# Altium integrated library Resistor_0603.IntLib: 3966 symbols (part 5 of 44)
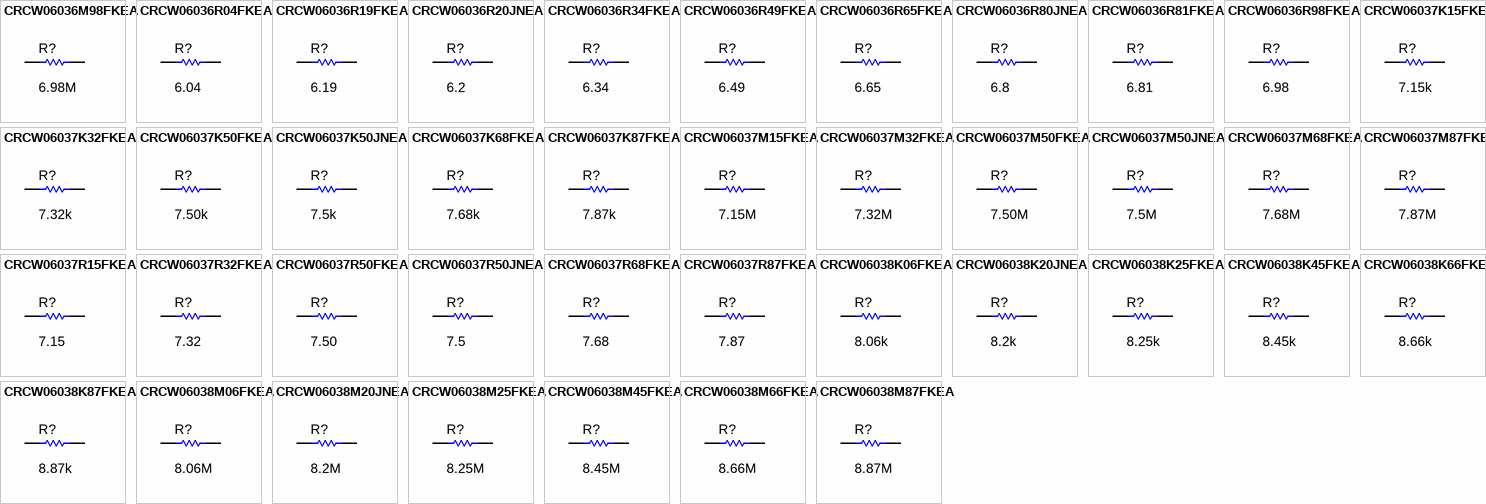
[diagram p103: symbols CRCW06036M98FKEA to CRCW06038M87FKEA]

## CRCW06038M66FKEA
designator R?  ValueDisplayed: 8.66M  (hidden comment: CRCW06038M66FKEA)
RES, 8.66 M, 1%, 0.1 W, 0603; Manufacturer: Vishay-Dale; CompType: Resistor; Value: 8.66Meg; Res_ohm: 8660000; Value_Code: 8M66; Tolerance_%: 1; Power_W: 0.1; Value2: 0.1W; VDC_V: 75; TempCo: 100 ppm/C; SizeArea_mm2: 1.28; SizeX_mm: 1.6; SizeY_mm: 0.8; EIA_Code: E96; U/M: EA; AEC Category: Q200; Green_Lifecycle: Active; Green_REACh: Passed
signal-integrity model Resistor
simulation model Resistor
footprint 0603
footprint 0603M
footprint 0603L
footprint 0603_HV
footprint 0603S
pins: 1, 2

## CRCW06038M87FKEA
designator R?  ValueDisplayed: 8.87M  (hidden comment: CRCW06038M87FKEA)
RES, 8.87 M, 1%, 0.1 W, 0603; Manufacturer: Vishay-Dale; CompType: Resistor; Value: 8.87Meg; Res_ohm: 8870000; Value_Code: 8M87; Tolerance_%: 1; Power_W: 0.1; Value2: 0.1W; VDC_V: 75; TempCo: 100 ppm/C; SizeArea_mm2: 1.28; SizeX_mm: 1.6; SizeY_mm: 0.8; EIA_Code: E96; U/M: EA; AEC Category: Q200
signal-integrity model Resistor
simulation model Resistor
footprint 0603
footprint 0603M
footprint 0603L
footprint 0603_HV
footprint 0603S
pins: 1, 2

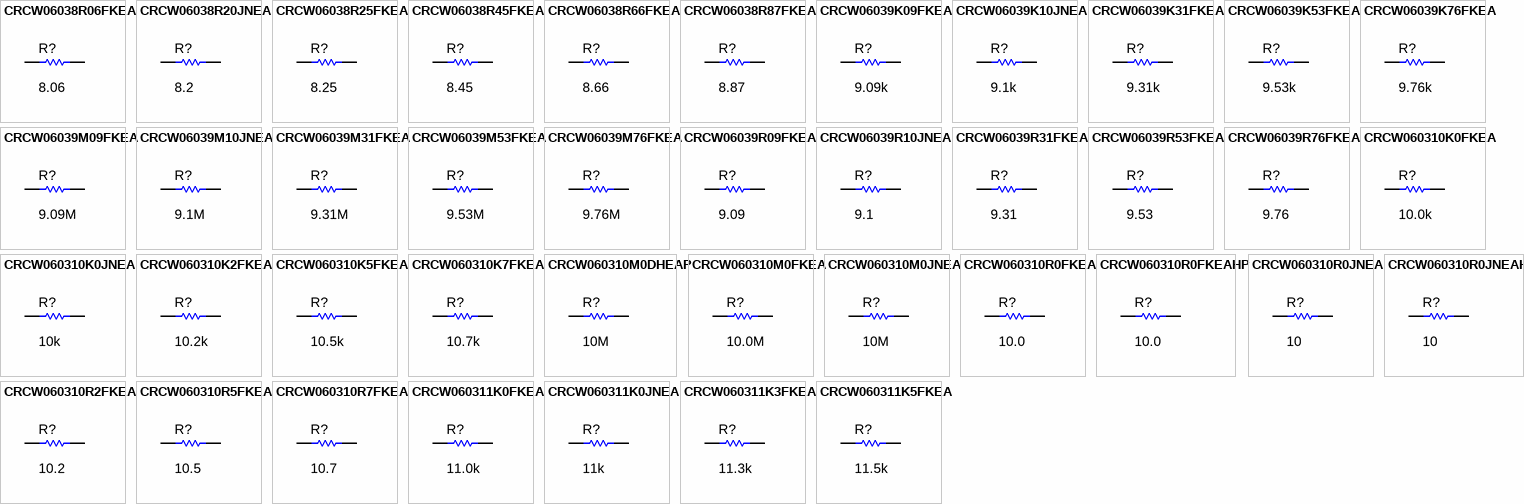
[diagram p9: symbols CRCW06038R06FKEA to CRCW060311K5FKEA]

## CRCW06038R06FKEA
designator R?  ValueDisplayed: 8.06  (hidden comment: CRCW06038R06FKEA)
RES, 8.06, 1%, 0.1 W, 0603; Manufacturer: Vishay-Dale; CompType: Resistor; Value: 8.06; Value_Code: 8R06; Tolerance_%: 1; Power_W: 0.1; Value2: 0.1W; VDC_V: 75; TempCo: 100 ppm/C; SizeArea_mm2: 1.28; SizeX_mm: 1.6; SizeY_mm: 0.8; EIA_Code: E96; U/M: EA; AEC Category: Q200
signal-integrity model Resistor
simulation model Resistor
footprint 0603
footprint 0603M
footprint 0603L
footprint 0603_HV
footprint 0603S
pins: 1, 2

## CRCW06038R20JNEA
designator R?  ValueDisplayed: 8.2  (hidden comment: CRCW06038R20JNEA)
RES, 8.2, 5%, 0.1 W, 0603; Manufacturer: Vishay-Dale; CompType: Resistor; Value: 8.2; Value_Code: 8R20; Tolerance_%: 5; Power_W: 0.1; Value2: 0.1W; VDC_V: 75; TempCo: 200 ppm/C; SizeArea_mm2: 1.28; SizeX_mm: 1.6; SizeY_mm: 0.8; SizeZ_mm: 1; EIA_Code: E24; U/M: EA; AEC Category: Q200
signal-integrity model Resistor
simulation model Resistor
footprint 0603
footprint 0603M
footprint 0603L
footprint 0603_HV
footprint 0603S
pins: 1, 2

## CRCW06038R25FKEA
designator R?  ValueDisplayed: 8.25  (hidden comment: CRCW06038R25FKEA)
RES, 8.25, 1%, 0.1 W, 0603; Manufacturer: Vishay-Dale; CompType: Resistor; Value: 8.25; Value_Code: 8R25; Tolerance_%: 1; Power_W: 0.1; Value2: 0.1W; VDC_V: 75; TempCo: 100 ppm/C; SizeArea_mm2: 1.28; SizeX_mm: 1.6; SizeY_mm: 0.8; EIA_Code: E96; U/M: EA; AEC Category: Q200
signal-integrity model Resistor
simulation model Resistor
footprint 0603
footprint 0603M
footprint 0603L
footprint 0603_HV
footprint 0603S
pins: 1, 2

## CRCW06038R45FKEA
designator R?  ValueDisplayed: 8.45  (hidden comment: CRCW06038R45FKEA)
RES, 8.45, 1%, 0.1 W, 0603; Manufacturer: Vishay-Dale; CompType: Resistor; Value: 8.45; Value_Code: 8R45; Tolerance_%: 1; Power_W: 0.1; Value2: 0.1W; VDC_V: 75; TempCo: 100 ppm/C; SizeArea_mm2: 1.28; SizeX_mm: 1.6; SizeY_mm: 0.8; EIA_Code: E96; U/M: EA; AEC Category: Q200
signal-integrity model Resistor
simulation model Resistor
footprint 0603
footprint 0603M
footprint 0603L
footprint 0603_HV
footprint 0603S
pins: 1, 2

## CRCW06038R66FKEA
designator R?  ValueDisplayed: 8.66  (hidden comment: CRCW06038R66FKEA)
RES, 8.66, 1%, 0.1 W, 0603; Manufacturer: Vishay-Dale; CompType: Resistor; Value: 8.66; Value_Code: 8R66; Tolerance_%: 1; Power_W: 0.1; Value2: 0.1W; VDC_V: 75; TempCo: 100 ppm/C; SizeArea_mm2: 1.28; SizeX_mm: 1.6; SizeY_mm: 0.8; EIA_Code: E96; U/M: EA; AEC Category: Q200
signal-integrity model Resistor
simulation model Resistor
footprint 0603
footprint 0603M
footprint 0603L
footprint 0603_HV
footprint 0603S
pins: 1, 2

## CRCW06038R87FKEA
designator R?  ValueDisplayed: 8.87  (hidden comment: CRCW06038R87FKEA)
RES, 8.87, 1%, 0.1 W, 0603; Manufacturer: Vishay-Dale; CompType: Resistor; Value: 8.87; Value_Code: 8R87; Tolerance_%: 1; Power_W: 0.1; Value2: 0.1W; VDC_V: 75; TempCo: 100 ppm/C; SizeArea_mm2: 1.28; SizeX_mm: 1.6; SizeY_mm: 0.8; EIA_Code: E96; U/M: EA; AEC Category: Q200
signal-integrity model Resistor
simulation model Resistor
footprint 0603
footprint 0603M
footprint 0603L
footprint 0603_HV
footprint 0603S
pins: 1, 2

## CRCW06039K09FKEA
designator R?  ValueDisplayed: 9.09k  (hidden comment: CRCW06039K09FKEA)
RES, 9.09 k, 1%, 0.1 W, 0603; Manufacturer: Vishay-Dale; CompType: Resistor; Value: 9.09k; Res_ohm: 9090; Value_Code: 9k09; Tolerance_%: 1; Power_W: 0.1; Value2: 0.1W; VDC_V: 75; TempCo: 100 ppm/C; SizeArea_mm2: 1.28; SizeX_mm: 1.6; SizeY_mm: 0.8; EIA_Code: E96; U/M: EA; AEC Category: Q200; Green_Lifecycle: Active; Green_REACh: Passed
signal-integrity model Resistor
simulation model Resistor
footprint 0603
footprint 0603M
footprint 0603L
footprint 0603_HV
footprint 0603S
pins: 1, 2

## CRCW06039K10JNEA
designator R?  ValueDisplayed: 9.1k  (hidden comment: CRCW06039K10JNEA)
RES, 9.1 k, 5%, 0.1 W, 0603; Manufacturer: Vishay-Dale; CompType: Resistor; Value: 9.1k; Res_ohm: 9100; Value_Code: 9k10; Tolerance_%: 5; Power_W: 0.1; Value2: 0.1W; VDC_V: 75; TempCo: 200 ppm/C; SizeArea_mm2: 1.28; SizeX_mm: 1.6; SizeY_mm: 0.8; SizeZ_mm: 1; EIA_Code: E24; U/M: EA; AEC Category: Q200; Green_Lifecycle: Active; Green_REACh: Passed
signal-integrity model Resistor
simulation model Resistor
footprint 0603
footprint 0603M
footprint 0603L
footprint 0603_HV
footprint 0603S
pins: 1, 2

## CRCW06039K31FKEA
designator R?  ValueDisplayed: 9.31k  (hidden comment: CRCW06039K31FKEA)
RES, 9.31 k, 1%, 0.1 W, 0603; Manufacturer: Vishay-Dale; CompType: Resistor; Value: 9.31k; Res_ohm: 9310; Value_Code: 9k31; Tolerance_%: 1; Power_W: 0.1; Value2: 0.1W; VDC_V: 75; TempCo: 100 ppm/C; SizeArea_mm2: 1.28; SizeX_mm: 1.6; SizeY_mm: 0.8; EIA_Code: E96; U/M: EA; AEC Category: Q200; Green_Lifecycle: Active; Green_REACh: Passed
signal-integrity model Resistor
simulation model Resistor
footprint 0603
footprint 0603M
footprint 0603L
footprint 0603_HV
footprint 0603S
pins: 1, 2

## CRCW06039K53FKEA
designator R?  ValueDisplayed: 9.53k  (hidden comment: CRCW06039K53FKEA)
RES, 9.53 k, 1%, 0.1 W, 0603; Manufacturer: Vishay-Dale; CompType: Resistor; Value: 9.53k; Res_ohm: 9530; Value_Code: 9k53; Tolerance_%: 1; Power_W: 0.1; Value2: 0.1W; VDC_V: 75; TempCo: 100 ppm/C; SizeArea_mm2: 1.28; SizeX_mm: 1.6; SizeY_mm: 0.8; EIA_Code: E96; U/M: EA; AEC Category: Q200; Green_Lifecycle: Active; Green_REACh: Passed
signal-integrity model Resistor
simulation model Resistor
footprint 0603
footprint 0603M
footprint 0603L
footprint 0603_HV
footprint 0603S
pins: 1, 2

## CRCW06039K76FKEA
designator R?  ValueDisplayed: 9.76k  (hidden comment: CRCW06039K76FKEA)
RES, 9.76 k, 1%, 0.1 W, 0603; Manufacturer: Vishay-Dale; CompType: Resistor; Value: 9.76k; Res_ohm: 9760; Value_Code: 9k76; Tolerance_%: 1; Power_W: 0.1; Value2: 0.1W; VDC_V: 75; TempCo: 100 ppm/C; SizeArea_mm2: 1.28; SizeX_mm: 1.6; SizeY_mm: 0.8; EIA_Code: E96; U/M: EA; AEC Category: Q200; Green_Lifecycle: Active; Green_REACh: Passed
signal-integrity model Resistor
simulation model Resistor
footprint 0603
footprint 0603M
footprint 0603L
footprint 0603_HV
footprint 0603S
pins: 1, 2

## CRCW06039M09FKEA
designator R?  ValueDisplayed: 9.09M  (hidden comment: CRCW06039M09FKEA)
RES, 9.09 M, 1%, 0.1 W, 0603; Manufacturer: Vishay-Dale; CompType: Resistor; Value: 9.09Meg; Res_ohm: 9090000; Value_Code: 9M09; Tolerance_%: 1; Power_W: 0.1; Value2: 0.1W; VDC_V: 75; TempCo: 100 ppm/C; SizeArea_mm2: 1.28; SizeX_mm: 1.6; SizeY_mm: 0.8; EIA_Code: E96; U/M: EA; AEC Category: Q200
signal-integrity model Resistor
simulation model Resistor
footprint 0603
footprint 0603M
footprint 0603L
footprint 0603_HV
footprint 0603S
pins: 1, 2

## CRCW06039M10JNEA
designator R?  ValueDisplayed: 9.1M  (hidden comment: CRCW06039M10JNEA)
RES, 9.1 M, 5%, 0.1 W, 0603; Manufacturer: Vishay-Dale; CompType: Resistor; Value: 9.1Meg; Res_ohm: 9100000; Value_Code: 9M10; Tolerance_%: 5; Power_W: 0.1; Value2: 0.1W; VDC_V: 75; TempCo: 200 ppm/C; SizeArea_mm2: 1.28; SizeX_mm: 1.6; SizeY_mm: 0.8; SizeZ_mm: 1; EIA_Code: E24; U/M: EA; AEC Category: Q200
signal-integrity model Resistor
simulation model Resistor
footprint 0603
footprint 0603M
footprint 0603L
footprint 0603_HV
footprint 0603S
pins: 1, 2

## CRCW06039M31FKEA
designator R?  ValueDisplayed: 9.31M  (hidden comment: CRCW06039M31FKEA)
RES, 9.31 M, 1%, 0.1 W, 0603; Manufacturer: Vishay-Dale; CompType: Resistor; Value: 9.31Meg; Res_ohm: 9310000; Value_Code: 9M31; Tolerance_%: 1; Power_W: 0.1; Value2: 0.1W; VDC_V: 75; TempCo: 100 ppm/C; SizeArea_mm2: 1.28; SizeX_mm: 1.6; SizeY_mm: 0.8; EIA_Code: E96; U/M: EA; AEC Category: Q200
signal-integrity model Resistor
simulation model Resistor
footprint 0603
footprint 0603M
footprint 0603L
footprint 0603_HV
footprint 0603S
pins: 1, 2

## CRCW06039M53FKEA
designator R?  ValueDisplayed: 9.53M  (hidden comment: CRCW06039M53FKEA)
RES, 9.53 M, 1%, 0.1 W, 0603; Manufacturer: Vishay-Dale; CompType: Resistor; Value: 9.53Meg; Res_ohm: 9530000; Value_Code: 9M53; Tolerance_%: 1; Power_W: 0.1; Value2: 0.1W; VDC_V: 75; TempCo: 100 ppm/C; SizeArea_mm2: 1.28; SizeX_mm: 1.6; SizeY_mm: 0.8; EIA_Code: E96; U/M: EA; AEC Category: Q200
signal-integrity model Resistor
simulation model Resistor
footprint 0603
footprint 0603M
footprint 0603L
footprint 0603_HV
footprint 0603S
pins: 1, 2

## CRCW06039M76FKEA
designator R?  ValueDisplayed: 9.76M  (hidden comment: CRCW06039M76FKEA)
RES, 9.76 M, 1%, 0.1 W, 0603; Manufacturer: Vishay-Dale; CompType: Resistor; Value: 9.76Meg; Res_ohm: 9760000; Value_Code: 9M76; Tolerance_%: 1; Power_W: 0.1; Value2: 0.1W; VDC_V: 75; TempCo: 100 ppm/C; SizeArea_mm2: 1.28; SizeX_mm: 1.6; SizeY_mm: 0.8; EIA_Code: E96; U/M: EA; AEC Category: Q200
signal-integrity model Resistor
simulation model Resistor
footprint 0603
footprint 0603M
footprint 0603L
footprint 0603_HV
footprint 0603S
pins: 1, 2

## CRCW06039R09FKEA
designator R?  ValueDisplayed: 9.09  (hidden comment: CRCW06039R09FKEA)
RES, 9.09, 1%, 0.1 W, 0603; Manufacturer: Vishay-Dale; CompType: Resistor; Value: 9.09; Value_Code: 9R09; Tolerance_%: 1; Power_W: 0.1; Value2: 0.1W; VDC_V: 75; TempCo: 100 ppm/C; SizeArea_mm2: 1.28; SizeX_mm: 1.6; SizeY_mm: 0.8; EIA_Code: E96; U/M: EA; AEC Category: Q200; Green_Lifecycle: Active; Green_REACh: Passed
signal-integrity model Resistor
simulation model Resistor
footprint 0603
footprint 0603M
footprint 0603L
footprint 0603_HV
footprint 0603S
pins: 1, 2

## CRCW06039R10JNEA
designator R?  ValueDisplayed: 9.1  (hidden comment: CRCW06039R10JNEA)
RES, 9.1, 5%, 0.1 W, 0603; Manufacturer: Vishay-Dale; CompType: Resistor; Value: 9.1; Value_Code: 9R10; Tolerance_%: 5; Power_W: 0.1; Value2: 0.1W; VDC_V: 75; TempCo: 200 ppm/C; SizeArea_mm2: 1.28; SizeX_mm: 1.6; SizeY_mm: 0.8; SizeZ_mm: 1; EIA_Code: E24; U/M: EA; AEC Category: Q200
signal-integrity model Resistor
simulation model Resistor
footprint 0603
footprint 0603M
footprint 0603L
footprint 0603_HV
footprint 0603S
pins: 1, 2

## CRCW06039R31FKEA
designator R?  ValueDisplayed: 9.31  (hidden comment: CRCW06039R31FKEA)
RES, 9.31, 1%, 0.1 W, 0603; Manufacturer: Vishay-Dale; CompType: Resistor; Value: 9.31; Value_Code: 9R31; Tolerance_%: 1; Power_W: 0.1; Value2: 0.1W; VDC_V: 75; TempCo: 100 ppm/C; SizeArea_mm2: 1.28; SizeX_mm: 1.6; SizeY_mm: 0.8; EIA_Code: E96; U/M: EA; AEC Category: Q200
signal-integrity model Resistor
simulation model Resistor
footprint 0603
footprint 0603M
footprint 0603L
footprint 0603_HV
footprint 0603S
pins: 1, 2

## CRCW06039R53FKEA
designator R?  ValueDisplayed: 9.53  (hidden comment: CRCW06039R53FKEA)
RES, 9.53, 1%, 0.1 W, 0603; Manufacturer: Vishay-Dale; CompType: Resistor; Value: 9.53; Value_Code: 9R53; Tolerance_%: 1; Power_W: 0.1; Value2: 0.1W; VDC_V: 75; TempCo: 100 ppm/C; SizeArea_mm2: 1.28; SizeX_mm: 1.6; SizeY_mm: 0.8; EIA_Code: E96; U/M: EA; AEC Category: Q200
signal-integrity model Resistor
simulation model Resistor
footprint 0603
footprint 0603M
footprint 0603L
footprint 0603_HV
footprint 0603S
pins: 1, 2

## CRCW06039R76FKEA
designator R?  ValueDisplayed: 9.76  (hidden comment: CRCW06039R76FKEA)
RES, 9.76, 1%, 0.1 W, 0603; Manufacturer: Vishay-Dale; CompType: Resistor; Value: 9.76; Value_Code: 9R76; Tolerance_%: 1; Power_W: 0.1; Value2: 0.1W; VDC_V: 75; TempCo: 100 ppm/C; SizeArea_mm2: 1.28; SizeX_mm: 1.6; SizeY_mm: 0.8; EIA_Code: E96; U/M: EA; AEC Category: Q200
signal-integrity model Resistor
simulation model Resistor
footprint 0603
footprint 0603M
footprint 0603L
footprint 0603_HV
footprint 0603S
pins: 1, 2

## CRCW060310K0FKEA
designator R?  ValueDisplayed: 10.0k  (hidden comment: CRCW060310K0FKEA)
RES, 10.0 k, 1%, 0.1 W, 0603; Manufacturer: Vishay-Dale; CompType: Resistor; Value: 10.0k; Res_ohm: 10000; Value_Code: 10k0; Tolerance_%: 1; Power_W: 0.1; Value2: 0.1W; VDC_V: 75; TempCo: 100 ppm/C; SizeArea_mm2: 1.28; SizeX_mm: 1.6; SizeY_mm: 0.8; EIA_Code: E96; U/M: EA; AEC Category: Q200; Green_Lifecycle: Active; Green_REACh: Passed
signal-integrity model Resistor
simulation model Resistor
footprint 0603
footprint 0603M
footprint 0603L
footprint 0603_HV
footprint 0603S
pins: 1, 2

## CRCW060310K0JNEA
designator R?  ValueDisplayed: 10k  (hidden comment: CRCW060310K0JNEA)
RES, 10 k, 5%, 0.1 W, 0603; Manufacturer: Vishay-Dale; CompType: Resistor; Value: 10k; Res_ohm: 10000; Value_Code: 10k0; Tolerance_%: 5; Power_W: 0.1; Value2: 0.1W; VDC_V: 75; TempCo: 200 ppm/C; SizeArea_mm2: 1.28; SizeX_mm: 1.6; SizeY_mm: 0.8; SizeZ_mm: 1; EIA_Code: E24; U/M: EA; AEC Category: Q200; Green_Lifecycle: Active; Green_REACh: Passed
signal-integrity model Resistor
simulation model Resistor
footprint 0603
footprint 0603M
footprint 0603L
footprint 0603_HV
footprint 0603S
pins: 1, 2

## CRCW060310K2FKEA
designator R?  ValueDisplayed: 10.2k  (hidden comment: CRCW060310K2FKEA)
RES, 10.2 k, 1%, 0.1 W, 0603; Manufacturer: Vishay-Dale; CompType: Resistor; Value: 10.2k; Res_ohm: 10200; Value_Code: 10k2; Tolerance_%: 1; Power_W: 0.1; Value2: 0.1W; VDC_V: 75; TempCo: 100 ppm/C; SizeArea_mm2: 1.28; SizeX_mm: 1.6; SizeY_mm: 0.8; EIA_Code: E96; U/M: EA; AEC Category: Q200; Green_Lifecycle: Active; Green_REACh: Passed
signal-integrity model Resistor
simulation model Resistor
footprint 0603
footprint 0603M
footprint 0603L
footprint 0603_HV
footprint 0603S
pins: 1, 2

## CRCW060310K5FKEA
designator R?  ValueDisplayed: 10.5k  (hidden comment: CRCW060310K5FKEA)
RES, 10.5 k, 1%, 0.1 W, 0603; Manufacturer: Vishay-Dale; CompType: Resistor; Value: 10.5k; Res_ohm: 10500; Value_Code: 10k5; Tolerance_%: 1; Power_W: 0.1; Value2: 0.1W; VDC_V: 75; TempCo: 100 ppm/C; SizeArea_mm2: 1.28; SizeX_mm: 1.6; SizeY_mm: 0.8; EIA_Code: E96; U/M: EA; AEC Category: Q200; Green_Lifecycle: Active; Green_REACh: Passed
signal-integrity model Resistor
simulation model Resistor
footprint 0603
footprint 0603M
footprint 0603L
footprint 0603_HV
footprint 0603S
pins: 1, 2

## CRCW060310K7FKEA
designator R?  ValueDisplayed: 10.7k  (hidden comment: CRCW060310K7FKEA)
RES, 10.7 k, 1%, 0.1 W, 0603; Manufacturer: Vishay-Dale; CompType: Resistor; Value: 10.7k; Res_ohm: 10700; Value_Code: 10k7; Tolerance_%: 1; Power_W: 0.1; Value2: 0.1W; VDC_V: 75; TempCo: 100 ppm/C; SizeArea_mm2: 1.28; SizeX_mm: 1.6; SizeY_mm: 0.8; EIA_Code: E96; U/M: EA; AEC Category: Q200; Green_Lifecycle: Active; Green_REACh: Passed
signal-integrity model Resistor
simulation model Resistor
footprint 0603
footprint 0603M
footprint 0603L
footprint 0603_HV
footprint 0603S
pins: 1, 2

## CRCW060310M0DHEAP
designator R?  ValueDisplayed: 10M  (hidden comment: CRCW060310M0DHEAP)
RES, 10 M, 0.5%, 0.1 W, AEC-Q200 Grade 0, 0603; Manufacturer: Vishay-Dale; CompType: Resistor; Value: 10Meg; Res_ohm: 10000000; Value_Code: 10M0; Tolerance_%: 0.5; Power_W: 0.1; Value2: 0.1W; VDC_V: 75; TempCo: 50 ppm/C; SizeArea_mm2: 1.28; SizeX_mm: 1.6; SizeY_mm: 0.8; SizeZ_mm: 1; EIA_Code: E24; U/M: EA; AEC Category: Q200; AEC Qualified: Y; AEC Grade: 0
signal-integrity model Resistor
simulation model Resistor
footprint 0603
footprint 0603M
footprint 0603L
footprint 0603_HV
footprint 0603S
pins: 1, 2

## CRCW060310M0FKEA
designator R?  ValueDisplayed: 10.0M  (hidden comment: CRCW060310M0FKEA)
RES, 10.0 M, 1%, 0.1 W, 0603; Manufacturer: Vishay-Dale; CompType: Resistor; Value: 10.0Meg; Res_ohm: 10000000; Value_Code: 10M0; Tolerance_%: 1; Power_W: 0.1; Value2: 0.1W; VDC_V: 75; TempCo: 100 ppm/C; SizeArea_mm2: 1.28; SizeX_mm: 1.6; SizeY_mm: 0.8; EIA_Code: E96; U/M: EA; AEC Category: Q200; Green_Lifecycle: Active; Green_REACh: Passed
signal-integrity model Resistor
simulation model Resistor
footprint 0603
footprint 0603M
footprint 0603L
footprint 0603_HV
footprint 0603S
pins: 1, 2

## CRCW060310M0JNEA
designator R?  ValueDisplayed: 10M  (hidden comment: CRCW060310M0JNEA)
RES, 10 M, 5%, 0.1 W, 0603; Manufacturer: Vishay-Dale; CompType: Resistor; Value: 10Meg; Res_ohm: 10000000; Value_Code: 10M0; Tolerance_%: 5; Power_W: 0.1; Value2: 0.1W; VDC_V: 75; TempCo: 200 ppm/C; SizeArea_mm2: 1.28; SizeX_mm: 1.6; SizeY_mm: 0.8; SizeZ_mm: 1; EIA_Code: E24; U/M: EA; AEC Category: Q200; Green_Lifecycle: Active; Green_REACh: Passed
signal-integrity model Resistor
simulation model Resistor
footprint 0603
footprint 0603M
footprint 0603L
footprint 0603_HV
footprint 0603S
pins: 1, 2

## CRCW060310R0FKEA
designator R?  ValueDisplayed: 10.0  (hidden comment: CRCW060310R0FKEA)
RES, 10.0, 1%, 0.1 W, 0603; Manufacturer: Vishay-Dale; CompType: Resistor; Value: 10.0; Res_ohm: 10; Value_Code: 10R0; Tolerance_%: 1; Power_W: 0.1; Value2: 0.1W; VDC_V: 75; TempCo: 100 ppm/C; SizeArea_mm2: 1.28; SizeX_mm: 1.6; SizeY_mm: 0.8; EIA_Code: E96; U/M: EA; AEC Category: Q200; Green_Lifecycle: Active; Green_REACh: Passed
signal-integrity model Resistor
simulation model Resistor
footprint 0603
footprint 0603M
footprint 0603L
footprint 0603_HV
footprint 0603S
pins: 1, 2

## CRCW060310R0FKEAHP
designator R?  ValueDisplayed: 10.0  (hidden comment: CRCW060310R0FKEAHP)
RES, 10.0, 1%, 0.25 W, 0603; Manufacturer: Vishay-Dale; CompType: Resistor; Value: 10.0; Res_ohm: 10; Value_Code: 10R0; Tolerance_%: 1; Power_W: 0.25; Value2: 0.25W; VDC_V: 75; TempCo: 100 ppm/C; SizeArea_mm2: 1.28; SizeX_mm: 1.6; SizeY_mm: 0.8; EIA_Code: E96; U/M: EA; AEC Category: Q200; Green_Lifecycle: Active; Green_REACh: Passed
signal-integrity model Resistor
simulation model Resistor
footprint 0603
footprint 0603M
footprint 0603L
footprint 0603_HV
footprint 0603S
pins: 1, 2

## CRCW060310R0JNEA
designator R?  ValueDisplayed: 10  (hidden comment: CRCW060310R0JNEA)
RES, 10, 5%, 0.1 W, 0603; Manufacturer: Vishay-Dale; CompType: Resistor; Value: 10; Value_Code: 10R0; Tolerance_%: 5; Power_W: 0.1; Value2: 0.1W; VDC_V: 75; TempCo: 200 ppm/C; SizeArea_mm2: 1.28; SizeX_mm: 1.6; SizeY_mm: 0.8; SizeZ_mm: 1; EIA_Code: E24; U/M: EA; AEC Category: Q200; Green_Lifecycle: Active; Green_REACh: Passed
signal-integrity model Resistor
simulation model Resistor
footprint 0603
footprint 0603M
footprint 0603L
footprint 0603_HV
footprint 0603S
pins: 1, 2

## CRCW060310R0JNEAHP
designator R?  ValueDisplayed: 10  (hidden comment: CRCW060310R0JNEAHP)
RES, 10, 5%, 0.25 W, 0603; Manufacturer: Vishay-Dale; CompType: Resistor; Value: 10; Value_Code: 10R0; Tolerance_%: 5; Power_W: 0.25; Value2: 0.25W; VDC_V: 75; TempCo: 200 ppm/C; SizeArea_mm2: 1.28; SizeX_mm: 1.6; SizeY_mm: 0.8; SizeZ_mm: 1; EIA_Code: E24; U/M: EA; AEC Category: Q200; Green_Lifecycle: Active; Green_REACh: Passed
signal-integrity model Resistor
simulation model Resistor
footprint 0603
footprint 0603M
footprint 0603L
footprint 0603_HV
footprint 0603S
pins: 1, 2

## CRCW060310R2FKEA
designator R?  ValueDisplayed: 10.2  (hidden comment: CRCW060310R2FKEA)
RES, 10.2, 1%, 0.1 W, 0603; Manufacturer: Vishay-Dale; CompType: Resistor; Value: 10.2; Value_Code: 10R2; Tolerance_%: 1; Power_W: 0.1; Value2: 0.1W; VDC_V: 75; TempCo: 100 ppm/C; SizeArea_mm2: 1.28; SizeX_mm: 1.6; SizeY_mm: 0.8; EIA_Code: E96; U/M: EA; AEC Category: Q200
signal-integrity model Resistor
simulation model Resistor
footprint 0603
footprint 0603M
footprint 0603L
footprint 0603_HV
footprint 0603S
pins: 1, 2

## CRCW060310R5FKEA
designator R?  ValueDisplayed: 10.5  (hidden comment: CRCW060310R5FKEA)
RES, 10.5, 1%, 0.1 W, 0603; Manufacturer: Vishay-Dale; CompType: Resistor; Value: 10.5; Value_Code: 10R5; Tolerance_%: 1; Power_W: 0.1; Value2: 0.1W; VDC_V: 75; TempCo: 100 ppm/C; SizeArea_mm2: 1.28; SizeX_mm: 1.6; SizeY_mm: 0.8; EIA_Code: E96; U/M: EA; AEC Category: Q200
signal-integrity model Resistor
simulation model Resistor
footprint 0603
footprint 0603M
footprint 0603L
footprint 0603_HV
footprint 0603S
pins: 1, 2

## CRCW060310R7FKEA
designator R?  ValueDisplayed: 10.7  (hidden comment: CRCW060310R7FKEA)
RES, 10.7, 1%, 0.1 W, 0603; Manufacturer: Vishay-Dale; CompType: Resistor; Value: 10.7; Value_Code: 10R7; Tolerance_%: 1; Power_W: 0.1; Value2: 0.1W; VDC_V: 75; TempCo: 100 ppm/C; SizeArea_mm2: 1.28; SizeX_mm: 1.6; SizeY_mm: 0.8; EIA_Code: E96; U/M: EA; AEC Category: Q200
signal-integrity model Resistor
simulation model Resistor
footprint 0603
footprint 0603M
footprint 0603L
footprint 0603_HV
footprint 0603S
pins: 1, 2

## CRCW060311K0FKEA
designator R?  ValueDisplayed: 11.0k  (hidden comment: CRCW060311K0FKEA)
RES, 11.0 k, 1%, 0.1 W, 0603; Manufacturer: Vishay-Dale; CompType: Resistor; Value: 11.0k; Res_ohm: 11000; Value_Code: 11k0; Tolerance_%: 1; Power_W: 0.1; Value2: 0.1W; VDC_V: 75; TempCo: 100 ppm/C; SizeArea_mm2: 1.28; SizeX_mm: 1.6; SizeY_mm: 0.8; EIA_Code: E96; U/M: EA; AEC Category: Q200; Green_Lifecycle: Not Set; Green_REACh: Incomplete
signal-integrity model Resistor
simulation model Resistor
footprint 0603
footprint 0603M
footprint 0603L
footprint 0603_HV
footprint 0603S
pins: 1, 2

## CRCW060311K0JNEA
designator R?  ValueDisplayed: 11k  (hidden comment: CRCW060311K0JNEA)
RES, 11 k, 5%, 0.1 W, 0603; Manufacturer: Vishay-Dale; CompType: Resistor; Value: 11k; Res_ohm: 11000; Value_Code: 11k0; Tolerance_%: 5; Power_W: 0.1; Value2: 0.1W; VDC_V: 75; TempCo: 200 ppm/C; SizeArea_mm2: 1.28; SizeX_mm: 1.6; SizeY_mm: 0.8; SizeZ_mm: 1; EIA_Code: E24; U/M: EA; AEC Category: Q200
signal-integrity model Resistor
simulation model Resistor
footprint 0603
footprint 0603M
footprint 0603L
footprint 0603_HV
footprint 0603S
pins: 1, 2

## CRCW060311K3FKEA
designator R?  ValueDisplayed: 11.3k  (hidden comment: CRCW060311K3FKEA)
RES, 11.3 k, 1%, 0.1 W, 0603; Manufacturer: Vishay-Dale; CompType: Resistor; Value: 11.3k; Res_ohm: 11300; Value_Code: 11k3; Tolerance_%: 1; Power_W: 0.1; Value2: 0.1W; VDC_V: 75; TempCo: 100 ppm/C; SizeArea_mm2: 1.28; SizeX_mm: 1.6; SizeY_mm: 0.8; EIA_Code: E96; U/M: EA; AEC Category: Q200; Green_Lifecycle: Active; Green_REACh: Passed
signal-integrity model Resistor
simulation model Resistor
footprint 0603
footprint 0603M
footprint 0603L
footprint 0603_HV
footprint 0603S
pins: 1, 2

## CRCW060311K5FKEA
designator R?  ValueDisplayed: 11.5k  (hidden comment: CRCW060311K5FKEA)
RES, 11.5 k, 1%, 0.1 W, 0603; Manufacturer: Vishay-Dale; CompType: Resistor; Value: 11.5k; Res_ohm: 11500; Value_Code: 11k5; Tolerance_%: 1; Power_W: 0.1; Value2: 0.1W; VDC_V: 75; TempCo: 100 ppm/C; SizeArea_mm2: 1.28; SizeX_mm: 1.6; SizeY_mm: 0.8; EIA_Code: E96; U/M: EA; AEC Category: Q200; Green_Lifecycle: Active; Green_REACh: Passed
signal-integrity model Resistor
simulation model Resistor
footprint 0603
footprint 0603M
footprint 0603L
footprint 0603_HV
footprint 0603S
pins: 1, 2

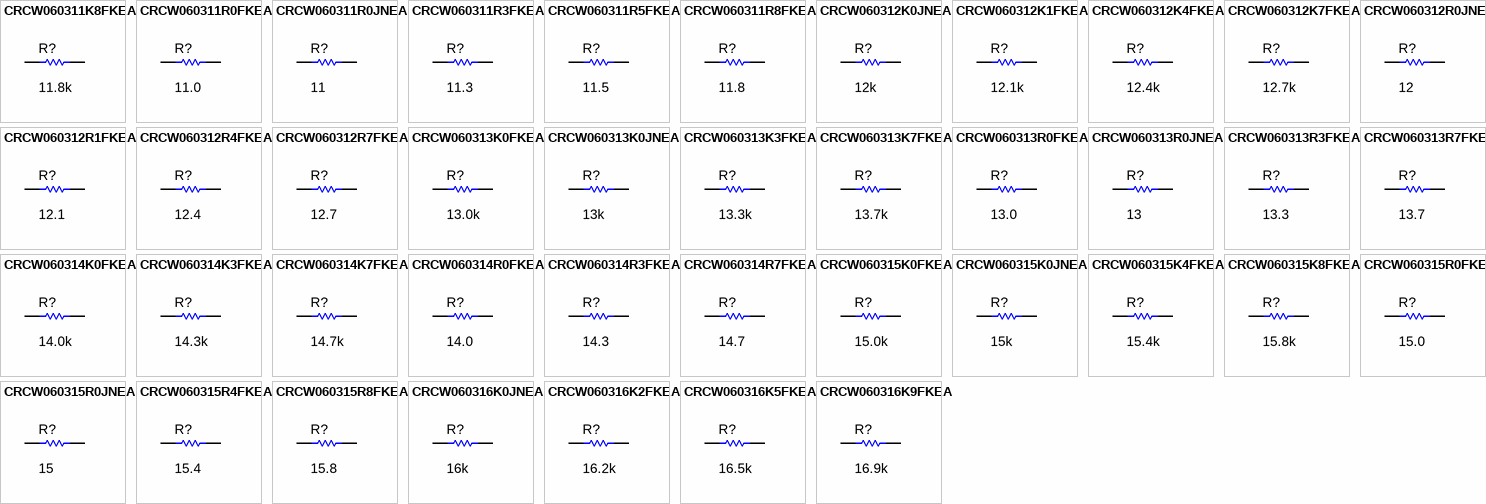
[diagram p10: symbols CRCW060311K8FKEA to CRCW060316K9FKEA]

## CRCW060311K8FKEA
designator R?  ValueDisplayed: 11.8k  (hidden comment: CRCW060311K8FKEA)
RES, 11.8 k, 1%, 0.1 W, 0603; Manufacturer: Vishay-Dale; CompType: Resistor; Value: 11.8k; Res_ohm: 11800; Value_Code: 11k8; Tolerance_%: 1; Power_W: 0.1; Value2: 0.1W; VDC_V: 75; TempCo: 100 ppm/C; SizeArea_mm2: 1.28; SizeX_mm: 1.6; SizeY_mm: 0.8; EIA_Code: E96; U/M: EA; AEC Category: Q200; Green_Lifecycle: Active; Green_REACh: Passed
signal-integrity model Resistor
simulation model Resistor
footprint 0603
footprint 0603M
footprint 0603L
footprint 0603_HV
footprint 0603S
pins: 1, 2

## CRCW060311R0FKEA
designator R?  ValueDisplayed: 11.0  (hidden comment: CRCW060311R0FKEA)
RES, 11.0, 1%, 0.1 W, 0603; Manufacturer: Vishay-Dale; CompType: Resistor; Value: 11.0; Res_ohm: 11; Value_Code: 11R0; Tolerance_%: 1; Power_W: 0.1; Value2: 0.1W; VDC_V: 75; TempCo: 100 ppm/C; SizeArea_mm2: 1.28; SizeX_mm: 1.6; SizeY_mm: 0.8; EIA_Code: E96; U/M: EA; AEC Category: Q200
signal-integrity model Resistor
simulation model Resistor
footprint 0603
footprint 0603M
footprint 0603L
footprint 0603_HV
footprint 0603S
pins: 1, 2

## CRCW060311R0JNEA
designator R?  ValueDisplayed: 11  (hidden comment: CRCW060311R0JNEA)
RES, 11, 5%, 0.1 W, 0603; Manufacturer: Vishay-Dale; CompType: Resistor; Value: 11; Value_Code: 11R0; Tolerance_%: 5; Power_W: 0.1; Value2: 0.1W; VDC_V: 75; TempCo: 200 ppm/C; SizeArea_mm2: 1.28; SizeX_mm: 1.6; SizeY_mm: 0.8; SizeZ_mm: 1; EIA_Code: E24; U/M: EA; AEC Category: Q200
signal-integrity model Resistor
simulation model Resistor
footprint 0603
footprint 0603M
footprint 0603L
footprint 0603_HV
footprint 0603S
pins: 1, 2

## CRCW060311R3FKEA
designator R?  ValueDisplayed: 11.3  (hidden comment: CRCW060311R3FKEA)
RES, 11.3, 1%, 0.1 W, 0603; Manufacturer: Vishay-Dale; CompType: Resistor; Value: 11.3; Value_Code: 11R3; Tolerance_%: 1; Power_W: 0.1; Value2: 0.1W; VDC_V: 75; TempCo: 100 ppm/C; SizeArea_mm2: 1.28; SizeX_mm: 1.6; SizeY_mm: 0.8; EIA_Code: E96; U/M: EA; AEC Category: Q200
signal-integrity model Resistor
simulation model Resistor
footprint 0603
footprint 0603M
footprint 0603L
footprint 0603_HV
footprint 0603S
pins: 1, 2

## CRCW060311R5FKEA
designator R?  ValueDisplayed: 11.5  (hidden comment: CRCW060311R5FKEA)
RES, 11.5, 1%, 0.1 W, 0603; Manufacturer: Vishay-Dale; CompType: Resistor; Value: 11.5; Value_Code: 11R5; Tolerance_%: 1; Power_W: 0.1; Value2: 0.1W; VDC_V: 75; TempCo: 100 ppm/C; SizeArea_mm2: 1.28; SizeX_mm: 1.6; SizeY_mm: 0.8; EIA_Code: E96; U/M: EA; AEC Category: Q200
signal-integrity model Resistor
simulation model Resistor
footprint 0603
footprint 0603M
footprint 0603L
footprint 0603_HV
footprint 0603S
pins: 1, 2

## CRCW060311R8FKEA
designator R?  ValueDisplayed: 11.8  (hidden comment: CRCW060311R8FKEA)
RES, 11.8, 1%, 0.1 W, 0603; Manufacturer: Vishay-Dale; CompType: Resistor; Value: 11.8; Value_Code: 11R8; Tolerance_%: 1; Power_W: 0.1; Value2: 0.1W; VDC_V: 75; TempCo: 100 ppm/C; SizeArea_mm2: 1.28; SizeX_mm: 1.6; SizeY_mm: 0.8; EIA_Code: E96; U/M: EA; AEC Category: Q200
signal-integrity model Resistor
simulation model Resistor
footprint 0603
footprint 0603M
footprint 0603L
footprint 0603_HV
footprint 0603S
pins: 1, 2

## CRCW060312K0JNEA
designator R?  ValueDisplayed: 12k  (hidden comment: CRCW060312K0JNEA)
RES, 12 k, 5%, 0.1 W, 0603; Manufacturer: Vishay-Dale; CompType: Resistor; Value: 12k; Res_ohm: 12000; Value_Code: 12k0; Tolerance_%: 5; Power_W: 0.1; Value2: 0.1W; VDC_V: 75; TempCo: 200 ppm/C; SizeArea_mm2: 1.28; SizeX_mm: 1.6; SizeY_mm: 0.8; SizeZ_mm: 1; EIA_Code: E24; U/M: EA; AEC Category: Q200; Green_Lifecycle: Active; Green_REACh: Passed
signal-integrity model Resistor
simulation model Resistor
footprint 0603
footprint 0603M
footprint 0603L
footprint 0603_HV
footprint 0603S
pins: 1, 2

## CRCW060312K1FKEA
designator R?  ValueDisplayed: 12.1k  (hidden comment: CRCW060312K1FKEA)
RES, 12.1 k, 1%, 0.1 W, 0603; Manufacturer: Vishay-Dale; CompType: Resistor; Value: 12.1k; Res_ohm: 12100; Value_Code: 12k1; Tolerance_%: 1; Power_W: 0.1; Value2: 0.1W; VDC_V: 75; TempCo: 100 ppm/C; SizeArea_mm2: 1.28; SizeX_mm: 1.6; SizeY_mm: 0.8; EIA_Code: E96; U/M: EA; AEC Category: Q200; Green_Lifecycle: Active; Green_REACh: Passed
signal-integrity model Resistor
simulation model Resistor
footprint 0603
footprint 0603M
footprint 0603L
footprint 0603_HV
footprint 0603S
pins: 1, 2

## CRCW060312K4FKEA
designator R?  ValueDisplayed: 12.4k  (hidden comment: CRCW060312K4FKEA)
RES, 12.4 k, 1%, 0.1 W, 0603; Manufacturer: Vishay-Dale; CompType: Resistor; Value: 12.4k; Res_ohm: 12400; Value_Code: 12k4; Tolerance_%: 1; Power_W: 0.1; Value2: 0.1W; VDC_V: 75; TempCo: 100 ppm/C; SizeArea_mm2: 1.28; SizeX_mm: 1.6; SizeY_mm: 0.8; EIA_Code: E96; U/M: EA; AEC Category: Q200; Green_Lifecycle: Active; Green_REACh: Passed
signal-integrity model Resistor
simulation model Resistor
footprint 0603
footprint 0603M
footprint 0603L
footprint 0603_HV
footprint 0603S
pins: 1, 2

## CRCW060312K7FKEA
designator R?  ValueDisplayed: 12.7k  (hidden comment: CRCW060312K7FKEA)
RES, 12.7 k, 1%, 0.1 W, 0603; Manufacturer: Vishay-Dale; CompType: Resistor; Value: 12.7k; Res_ohm: 12700; Value_Code: 12k7; Tolerance_%: 1; Power_W: 0.1; Value2: 0.1W; VDC_V: 75; TempCo: 100 ppm/C; SizeArea_mm2: 1.28; SizeX_mm: 1.6; SizeY_mm: 0.8; EIA_Code: E96; U/M: EA; AEC Category: Q200; Green_Lifecycle: Active; Green_REACh: Passed
signal-integrity model Resistor
simulation model Resistor
footprint 0603
footprint 0603M
footprint 0603L
footprint 0603_HV
footprint 0603S
pins: 1, 2

## CRCW060312R0JNEA
designator R?  ValueDisplayed: 12  (hidden comment: CRCW060312R0JNEA)
RES, 12, 5%, 0.1 W, 0603; Manufacturer: Vishay-Dale; CompType: Resistor; Value: 12; Value_Code: 12R0; Tolerance_%: 5; Power_W: 0.1; Value2: 0.1W; VDC_V: 75; TempCo: 200 ppm/C; SizeArea_mm2: 1.28; SizeX_mm: 1.6; SizeY_mm: 0.8; SizeZ_mm: 1; EIA_Code: E24; U/M: EA; AEC Category: Q200; Green_Lifecycle: Active; Green_REACh: Passed
signal-integrity model Resistor
simulation model Resistor
footprint 0603
footprint 0603M
footprint 0603L
footprint 0603_HV
footprint 0603S
pins: 1, 2

## CRCW060312R1FKEA
designator R?  ValueDisplayed: 12.1  (hidden comment: CRCW060312R1FKEA)
RES, 12.1, 1%, 0.1 W, 0603; Manufacturer: Vishay-Dale; CompType: Resistor; Value: 12.1; Value_Code: 12R1; Tolerance_%: 1; Power_W: 0.1; Value2: 0.1W; VDC_V: 75; TempCo: 100 ppm/C; SizeArea_mm2: 1.28; SizeX_mm: 1.6; SizeY_mm: 0.8; EIA_Code: E96; U/M: EA; AEC Category: Q200
signal-integrity model Resistor
simulation model Resistor
footprint 0603
footprint 0603M
footprint 0603L
footprint 0603_HV
footprint 0603S
pins: 1, 2

## CRCW060312R4FKEA
designator R?  ValueDisplayed: 12.4  (hidden comment: CRCW060312R4FKEA)
RES, 12.4, 1%, 0.1 W, 0603; Manufacturer: Vishay-Dale; CompType: Resistor; Value: 12.4; Value_Code: 12R4; Tolerance_%: 1; Power_W: 0.1; Value2: 0.1W; VDC_V: 75; TempCo: 100 ppm/C; SizeArea_mm2: 1.28; SizeX_mm: 1.6; SizeY_mm: 0.8; EIA_Code: E96; U/M: EA; AEC Category: Q200
signal-integrity model Resistor
simulation model Resistor
footprint 0603
footprint 0603M
footprint 0603L
footprint 0603_HV
footprint 0603S
pins: 1, 2

## CRCW060312R7FKEA
designator R?  ValueDisplayed: 12.7  (hidden comment: CRCW060312R7FKEA)
RES, 12.7, 1%, 0.1 W, 0603; Manufacturer: Vishay-Dale; CompType: Resistor; Value: 12.7; Value_Code: 12R7; Tolerance_%: 1; Power_W: 0.1; Value2: 0.1W; VDC_V: 75; TempCo: 100 ppm/C; SizeArea_mm2: 1.28; SizeX_mm: 1.6; SizeY_mm: 0.8; EIA_Code: E96; U/M: EA; AEC Category: Q200
signal-integrity model Resistor
simulation model Resistor
footprint 0603
footprint 0603M
footprint 0603L
footprint 0603_HV
footprint 0603S
pins: 1, 2

## CRCW060313K0FKEA
designator R?  ValueDisplayed: 13.0k  (hidden comment: CRCW060313K0FKEA)
RES, 13.0 k, 1%, 0.1 W, 0603; Manufacturer: Vishay-Dale; CompType: Resistor; Value: 13.0k; Res_ohm: 13000; Value_Code: 13k0; Tolerance_%: 1; Power_W: 0.1; Value2: 0.1W; VDC_V: 75; TempCo: 100 ppm/C; SizeArea_mm2: 1.28; SizeX_mm: 1.6; SizeY_mm: 0.8; EIA_Code: E96; U/M: EA; AEC Category: Q200; Green_Lifecycle: Active; Green_REACh: Passed
signal-integrity model Resistor
simulation model Resistor
footprint 0603
footprint 0603M
footprint 0603L
footprint 0603_HV
footprint 0603S
pins: 1, 2

## CRCW060313K0JNEA
designator R?  ValueDisplayed: 13k  (hidden comment: CRCW060313K0JNEA)
RES, 13 k, 5%, 0.1 W, 0603; Manufacturer: Vishay-Dale; CompType: Resistor; Value: 13k; Res_ohm: 13000; Value_Code: 13k0; Tolerance_%: 5; Power_W: 0.1; Value2: 0.1W; VDC_V: 75; TempCo: 200 ppm/C; SizeArea_mm2: 1.28; SizeX_mm: 1.6; SizeY_mm: 0.8; SizeZ_mm: 1; EIA_Code: E24; U/M: EA; AEC Category: Q200; Green_Lifecycle: Active; Green_REACh: Passed
signal-integrity model Resistor
simulation model Resistor
footprint 0603
footprint 0603M
footprint 0603L
footprint 0603_HV
footprint 0603S
pins: 1, 2

## CRCW060313K3FKEA
designator R?  ValueDisplayed: 13.3k  (hidden comment: CRCW060313K3FKEA)
RES, 13.3 k, 1%, 0.1 W, 0603; Manufacturer: Vishay-Dale; CompType: Resistor; Value: 13.3k; Res_ohm: 13300; Value_Code: 13k3; Tolerance_%: 1; Power_W: 0.1; Value2: 0.1W; VDC_V: 75; TempCo: 100 ppm/C; SizeArea_mm2: 1.28; SizeX_mm: 1.6; SizeY_mm: 0.8; EIA_Code: E96; U/M: EA; AEC Category: Q200; Green_Lifecycle: Active; Green_REACh: Passed
signal-integrity model Resistor
simulation model Resistor
footprint 0603
footprint 0603M
footprint 0603L
footprint 0603_HV
footprint 0603S
pins: 1, 2

## CRCW060313K7FKEA
designator R?  ValueDisplayed: 13.7k  (hidden comment: CRCW060313K7FKEA)
RES, 13.7 k, 1%, 0.1 W, 0603; Manufacturer: Vishay-Dale; CompType: Resistor; Value: 13.7k; Res_ohm: 13700; Value_Code: 13k7; Tolerance_%: 1; Power_W: 0.1; Value2: 0.1W; VDC_V: 75; TempCo: 100 ppm/C; SizeArea_mm2: 1.28; SizeX_mm: 1.6; SizeY_mm: 0.8; EIA_Code: E96; U/M: EA; AEC Category: Q200; Green_Lifecycle: Active; Green_REACh: Passed
signal-integrity model Resistor
simulation model Resistor
footprint 0603
footprint 0603M
footprint 0603L
footprint 0603_HV
footprint 0603S
pins: 1, 2

## CRCW060313R0FKEA
designator R?  ValueDisplayed: 13.0  (hidden comment: CRCW060313R0FKEA)
RES, 13.0, 1%, 0.1 W, 0603; Manufacturer: Vishay-Dale; CompType: Resistor; Value: 13.0; Res_ohm: 13; Value_Code: 13R0; Tolerance_%: 1; Power_W: 0.1; Value2: 0.1W; VDC_V: 75; TempCo: 100 ppm/C; SizeArea_mm2: 1.28; SizeX_mm: 1.6; SizeY_mm: 0.8; EIA_Code: E96; U/M: EA; AEC Category: Q200
signal-integrity model Resistor
simulation model Resistor
footprint 0603
footprint 0603M
footprint 0603L
footprint 0603_HV
footprint 0603S
pins: 1, 2

## CRCW060313R0JNEA
designator R?  ValueDisplayed: 13  (hidden comment: CRCW060313R0JNEA)
RES, 13, 5%, 0.1 W, 0603; Manufacturer: Vishay-Dale; CompType: Resistor; Value: 13; Value_Code: 13R0; Tolerance_%: 5; Power_W: 0.1; Value2: 0.1W; VDC_V: 75; TempCo: 200 ppm/C; SizeArea_mm2: 1.28; SizeX_mm: 1.6; SizeY_mm: 0.8; SizeZ_mm: 1; EIA_Code: E24; U/M: EA; AEC Category: Q200
signal-integrity model Resistor
simulation model Resistor
footprint 0603
footprint 0603M
footprint 0603L
footprint 0603_HV
footprint 0603S
pins: 1, 2

## CRCW060313R3FKEA
designator R?  ValueDisplayed: 13.3  (hidden comment: CRCW060313R3FKEA)
RES, 13.3, 1%, 0.1 W, 0603; Manufacturer: Vishay-Dale; CompType: Resistor; Value: 13.3; Value_Code: 13R3; Tolerance_%: 1; Power_W: 0.1; Value2: 0.1W; VDC_V: 75; TempCo: 100 ppm/C; SizeArea_mm2: 1.28; SizeX_mm: 1.6; SizeY_mm: 0.8; EIA_Code: E96; U/M: EA; AEC Category: Q200
signal-integrity model Resistor
simulation model Resistor
footprint 0603
footprint 0603M
footprint 0603L
footprint 0603_HV
footprint 0603S
pins: 1, 2

## CRCW060313R7FKEA
designator R?  ValueDisplayed: 13.7  (hidden comment: CRCW060313R7FKEA)
RES, 13.7, 1%, 0.1 W, 0603; Manufacturer: Vishay-Dale; CompType: Resistor; Value: 13.7; Value_Code: 13R7; Tolerance_%: 1; Power_W: 0.1; Value2: 0.1W; VDC_V: 75; TempCo: 100 ppm/C; SizeArea_mm2: 1.28; SizeX_mm: 1.6; SizeY_mm: 0.8; EIA_Code: E96; U/M: EA; AEC Category: Q200
signal-integrity model Resistor
simulation model Resistor
footprint 0603
footprint 0603M
footprint 0603L
footprint 0603_HV
footprint 0603S
pins: 1, 2

## CRCW060314K0FKEA
designator R?  ValueDisplayed: 14.0k  (hidden comment: CRCW060314K0FKEA)
RES, 14.0 k, 1%, 0.1 W, 0603; Manufacturer: Vishay-Dale; CompType: Resistor; Value: 14.0k; Res_ohm: 14000; Value_Code: 14k0; Tolerance_%: 1; Power_W: 0.1; Value2: 0.1W; VDC_V: 75; TempCo: 100 ppm/C; SizeArea_mm2: 1.28; SizeX_mm: 1.6; SizeY_mm: 0.8; EIA_Code: E96; U/M: EA; AEC Category: Q200; Green_Lifecycle: Active; Green_REACh: Passed
signal-integrity model Resistor
simulation model Resistor
footprint 0603
footprint 0603M
footprint 0603L
footprint 0603_HV
footprint 0603S
pins: 1, 2

## CRCW060314K3FKEA
designator R?  ValueDisplayed: 14.3k  (hidden comment: CRCW060314K3FKEA)
RES, 14.3 k, 1%, 0.1 W, 0603; Manufacturer: Vishay-Dale; CompType: Resistor; Value: 14.3k; Res_ohm: 14300; Value_Code: 14k3; Tolerance_%: 1; Power_W: 0.1; Value2: 0.1W; VDC_V: 75; TempCo: 100 ppm/C; SizeArea_mm2: 1.28; SizeX_mm: 1.6; SizeY_mm: 0.8; EIA_Code: E96; U/M: EA; AEC Category: Q200; Green_Lifecycle: Active; Green_REACh: Passed
signal-integrity model Resistor
simulation model Resistor
footprint 0603
footprint 0603M
footprint 0603L
footprint 0603_HV
footprint 0603S
pins: 1, 2

## CRCW060314K7FKEA
designator R?  ValueDisplayed: 14.7k  (hidden comment: CRCW060314K7FKEA)
RES, 14.7 k, 1%, 0.1 W, 0603; Manufacturer: Vishay-Dale; CompType: Resistor; Value: 14.7k; Res_ohm: 14700; Value_Code: 14k7; Tolerance_%: 1; Power_W: 0.1; Value2: 0.1W; VDC_V: 75; TempCo: 100 ppm/C; SizeArea_mm2: 1.28; SizeX_mm: 1.6; SizeY_mm: 0.8; EIA_Code: E96; U/M: EA; AEC Category: Q200; Green_Lifecycle: Active; Green_REACh: Passed
signal-integrity model Resistor
simulation model Resistor
footprint 0603
footprint 0603M
footprint 0603L
footprint 0603_HV
footprint 0603S
pins: 1, 2

## CRCW060314R0FKEA
designator R?  ValueDisplayed: 14.0  (hidden comment: CRCW060314R0FKEA)
RES, 14.0, 1%, 0.1 W, 0603; Manufacturer: Vishay-Dale; CompType: Resistor; Value: 14.0; Res_ohm: 14; Value_Code: 14R0; Tolerance_%: 1; Power_W: 0.1; Value2: 0.1W; VDC_V: 75; TempCo: 100 ppm/C; SizeArea_mm2: 1.28; SizeX_mm: 1.6; SizeY_mm: 0.8; EIA_Code: E96; U/M: EA; AEC Category: Q200
signal-integrity model Resistor
simulation model Resistor
footprint 0603
footprint 0603M
footprint 0603L
footprint 0603_HV
footprint 0603S
pins: 1, 2

## CRCW060314R3FKEA
designator R?  ValueDisplayed: 14.3  (hidden comment: CRCW060314R3FKEA)
RES, 14.3, 1%, 0.1 W, 0603; Manufacturer: Vishay-Dale; CompType: Resistor; Value: 14.3; Value_Code: 14R3; Tolerance_%: 1; Power_W: 0.1; Value2: 0.1W; VDC_V: 75; TempCo: 100 ppm/C; SizeArea_mm2: 1.28; SizeX_mm: 1.6; SizeY_mm: 0.8; EIA_Code: E96; U/M: EA; AEC Category: Q200
signal-integrity model Resistor
simulation model Resistor
footprint 0603
footprint 0603M
footprint 0603L
footprint 0603_HV
footprint 0603S
pins: 1, 2

## CRCW060314R7FKEA
designator R?  ValueDisplayed: 14.7  (hidden comment: CRCW060314R7FKEA)
RES, 14.7, 1%, 0.1 W, 0603; Manufacturer: Vishay-Dale; CompType: Resistor; Value: 14.7; Value_Code: 14R7; Tolerance_%: 1; Power_W: 0.1; Value2: 0.1W; VDC_V: 75; TempCo: 100 ppm/C; SizeArea_mm2: 1.28; SizeX_mm: 1.6; SizeY_mm: 0.8; EIA_Code: E96; U/M: EA; AEC Category: Q200
signal-integrity model Resistor
simulation model Resistor
footprint 0603
footprint 0603M
footprint 0603L
footprint 0603_HV
footprint 0603S
pins: 1, 2

## CRCW060315K0FKEA
designator R?  ValueDisplayed: 15.0k  (hidden comment: CRCW060315K0FKEA)
RES, 15.0 k, 1%, 0.1 W, 0603; Manufacturer: Vishay-Dale; CompType: Resistor; Value: 15.0k; Res_ohm: 15000; Value_Code: 15k0; Tolerance_%: 1; Power_W: 0.1; Value2: 0.1W; VDC_V: 75; TempCo: 100 ppm/C; SizeArea_mm2: 1.28; SizeX_mm: 1.6; SizeY_mm: 0.8; EIA_Code: E96; U/M: EA; AEC Category: Q200; Green_Lifecycle: Active; Green_REACh: Passed
signal-integrity model Resistor
simulation model Resistor
footprint 0603
footprint 0603M
footprint 0603L
footprint 0603_HV
footprint 0603S
pins: 1, 2

## CRCW060315K0JNEA
designator R?  ValueDisplayed: 15k  (hidden comment: CRCW060315K0JNEA)
RES, 15 k, 5%, 0.1 W, 0603; Manufacturer: Vishay-Dale; CompType: Resistor; Value: 15k; Res_ohm: 15000; Value_Code: 15k0; Tolerance_%: 5; Power_W: 0.1; Value2: 0.1W; VDC_V: 75; TempCo: 200 ppm/C; SizeArea_mm2: 1.28; SizeX_mm: 1.6; SizeY_mm: 0.8; SizeZ_mm: 1; EIA_Code: E24; U/M: EA; AEC Category: Q200; Green_Lifecycle: Active; Green_REACh: Passed
signal-integrity model Resistor
simulation model Resistor
footprint 0603
footprint 0603M
footprint 0603L
footprint 0603_HV
footprint 0603S
pins: 1, 2

## CRCW060315K4FKEA
designator R?  ValueDisplayed: 15.4k  (hidden comment: CRCW060315K4FKEA)
RES, 15.4 k, 1%, 0.1 W, 0603; Manufacturer: Vishay-Dale; CompType: Resistor; Value: 15.4k; Res_ohm: 15400; Value_Code: 15k4; Tolerance_%: 1; Power_W: 0.1; Value2: 0.1W; VDC_V: 75; TempCo: 100 ppm/C; SizeArea_mm2: 1.28; SizeX_mm: 1.6; SizeY_mm: 0.8; EIA_Code: E96; U/M: EA; AEC Category: Q200; Green_Lifecycle: Active; Green_REACh: Passed
signal-integrity model Resistor
simulation model Resistor
footprint 0603
footprint 0603M
footprint 0603L
footprint 0603_HV
footprint 0603S
pins: 1, 2

## CRCW060315K8FKEA
designator R?  ValueDisplayed: 15.8k  (hidden comment: CRCW060315K8FKEA)
RES, 15.8 k, 1%, 0.1 W, 0603; Manufacturer: Vishay-Dale; CompType: Resistor; Value: 15.8k; Res_ohm: 15800; Value_Code: 15k8; Tolerance_%: 1; Power_W: 0.1; Value2: 0.1W; VDC_V: 75; TempCo: 100 ppm/C; SizeArea_mm2: 1.28; SizeX_mm: 1.6; SizeY_mm: 0.8; EIA_Code: E96; U/M: EA; AEC Category: Q200; Green_Lifecycle: Active; Green_REACh: Passed
signal-integrity model Resistor
simulation model Resistor
footprint 0603
footprint 0603M
footprint 0603L
footprint 0603_HV
footprint 0603S
pins: 1, 2

## CRCW060315R0FKEA
designator R?  ValueDisplayed: 15.0  (hidden comment: CRCW060315R0FKEA)
RES, 15.0, 1%, 0.1 W, 0603; Manufacturer: Vishay-Dale; CompType: Resistor; Value: 15.0; Res_ohm: 15; Value_Code: 15R0; Tolerance_%: 1; Power_W: 0.1; Value2: 0.1W; VDC_V: 75; TempCo: 100 ppm/C; SizeArea_mm2: 1.28; SizeX_mm: 1.6; SizeY_mm: 0.8; EIA_Code: E96; U/M: EA; AEC Category: Q200; Green_Lifecycle: Active; Green_REACh: Passed
signal-integrity model Resistor
simulation model Resistor
footprint 0603
footprint 0603M
footprint 0603L
footprint 0603_HV
footprint 0603S
pins: 1, 2

## CRCW060315R0JNEA
designator R?  ValueDisplayed: 15  (hidden comment: CRCW060315R0JNEA)
RES, 15, 5%, 0.1 W, 0603; Manufacturer: Vishay-Dale; CompType: Resistor; Value: 15; Value_Code: 15R0; Tolerance_%: 5; Power_W: 0.1; Value2: 0.1W; VDC_V: 75; TempCo: 200 ppm/C; SizeArea_mm2: 1.28; SizeX_mm: 1.6; SizeY_mm: 0.8; SizeZ_mm: 1; EIA_Code: E24; U/M: EA; AEC Category: Q200; Green_Lifecycle: Active; Green_REACh: Passed
signal-integrity model Resistor
simulation model Resistor
footprint 0603
footprint 0603M
footprint 0603L
footprint 0603_HV
footprint 0603S
pins: 1, 2

## CRCW060315R4FKEA
designator R?  ValueDisplayed: 15.4  (hidden comment: CRCW060315R4FKEA)
RES, 15.4, 1%, 0.1 W, 0603; Manufacturer: Vishay-Dale; CompType: Resistor; Value: 15.4; Value_Code: 15R4; Tolerance_%: 1; Power_W: 0.1; Value2: 0.1W; VDC_V: 75; TempCo: 100 ppm/C; SizeArea_mm2: 1.28; SizeX_mm: 1.6; SizeY_mm: 0.8; EIA_Code: E96; U/M: EA; AEC Category: Q200
signal-integrity model Resistor
simulation model Resistor
footprint 0603
footprint 0603M
footprint 0603L
footprint 0603_HV
footprint 0603S
pins: 1, 2

## CRCW060315R8FKEA
designator R?  ValueDisplayed: 15.8  (hidden comment: CRCW060315R8FKEA)
RES, 15.8, 1%, 0.1 W, 0603; Manufacturer: Vishay-Dale; CompType: Resistor; Value: 15.8; Value_Code: 15R8; Tolerance_%: 1; Power_W: 0.1; Value2: 0.1W; VDC_V: 75; TempCo: 100 ppm/C; SizeArea_mm2: 1.28; SizeX_mm: 1.6; SizeY_mm: 0.8; EIA_Code: E96; U/M: EA; AEC Category: Q200
signal-integrity model Resistor
simulation model Resistor
footprint 0603
footprint 0603M
footprint 0603L
footprint 0603_HV
footprint 0603S
pins: 1, 2

## CRCW060316K0JNEA
designator R?  ValueDisplayed: 16k  (hidden comment: CRCW060316K0JNEA)
RES, 16 k, 5%, 0.1 W, 0603; Manufacturer: Vishay-Dale; CompType: Resistor; Value: 16k; Res_ohm: 16000; Value_Code: 16k0; Tolerance_%: 5; Power_W: 0.1; Value2: 0.1W; VDC_V: 75; TempCo: 200 ppm/C; SizeArea_mm2: 1.28; SizeX_mm: 1.6; SizeY_mm: 0.8; SizeZ_mm: 1; EIA_Code: E24; U/M: EA; AEC Category: Q200
signal-integrity model Resistor
simulation model Resistor
footprint 0603
footprint 0603M
footprint 0603L
footprint 0603_HV
footprint 0603S
pins: 1, 2

## CRCW060316K2FKEA
designator R?  ValueDisplayed: 16.2k  (hidden comment: CRCW060316K2FKEA)
RES, 16.2 k, 1%, 0.1 W, 0603; Manufacturer: Vishay-Dale; CompType: Resistor; Value: 16.2k; Res_ohm: 16200; Value_Code: 16k2; Tolerance_%: 1; Power_W: 0.1; Value2: 0.1W; VDC_V: 75; TempCo: 100 ppm/C; SizeArea_mm2: 1.28; SizeX_mm: 1.6; SizeY_mm: 0.8; EIA_Code: E96; U/M: EA; AEC Category: Q200; Green_Lifecycle: Active; Green_REACh: Passed
signal-integrity model Resistor
simulation model Resistor
footprint 0603
footprint 0603M
footprint 0603L
footprint 0603_HV
footprint 0603S
pins: 1, 2

## CRCW060316K5FKEA
designator R?  ValueDisplayed: 16.5k  (hidden comment: CRCW060316K5FKEA)
RES, 16.5 k, 1%, 0.1 W, 0603; Manufacturer: Vishay-Dale; CompType: Resistor; Value: 16.5k; Res_ohm: 16500; Value_Code: 16k5; Tolerance_%: 1; Power_W: 0.1; Value2: 0.1W; VDC_V: 75; TempCo: 100 ppm/C; SizeArea_mm2: 1.28; SizeX_mm: 1.6; SizeY_mm: 0.8; EIA_Code: E96; U/M: EA; AEC Category: Q200; Green_Lifecycle: Active; Green_REACh: Passed
signal-integrity model Resistor
simulation model Resistor
footprint 0603
footprint 0603M
footprint 0603L
footprint 0603_HV
footprint 0603S
pins: 1, 2

## CRCW060316K9FKEA
designator R?  ValueDisplayed: 16.9k  (hidden comment: CRCW060316K9FKEA)
RES, 16.9 k, 1%, 0.1 W, 0603; Manufacturer: Vishay-Dale; CompType: Resistor; Value: 16.9k; Res_ohm: 16900; Value_Code: 16k9; Tolerance_%: 1; Power_W: 0.1; Value2: 0.1W; VDC_V: 75; TempCo: 100 ppm/C; SizeArea_mm2: 1.28; SizeX_mm: 1.6; SizeY_mm: 0.8; EIA_Code: E96; U/M: EA; AEC Category: Q200; Green_Lifecycle: Active; Green_REACh: Passed
signal-integrity model Resistor
simulation model Resistor
footprint 0603
footprint 0603M
footprint 0603L
footprint 0603_HV
footprint 0603S
pins: 1, 2

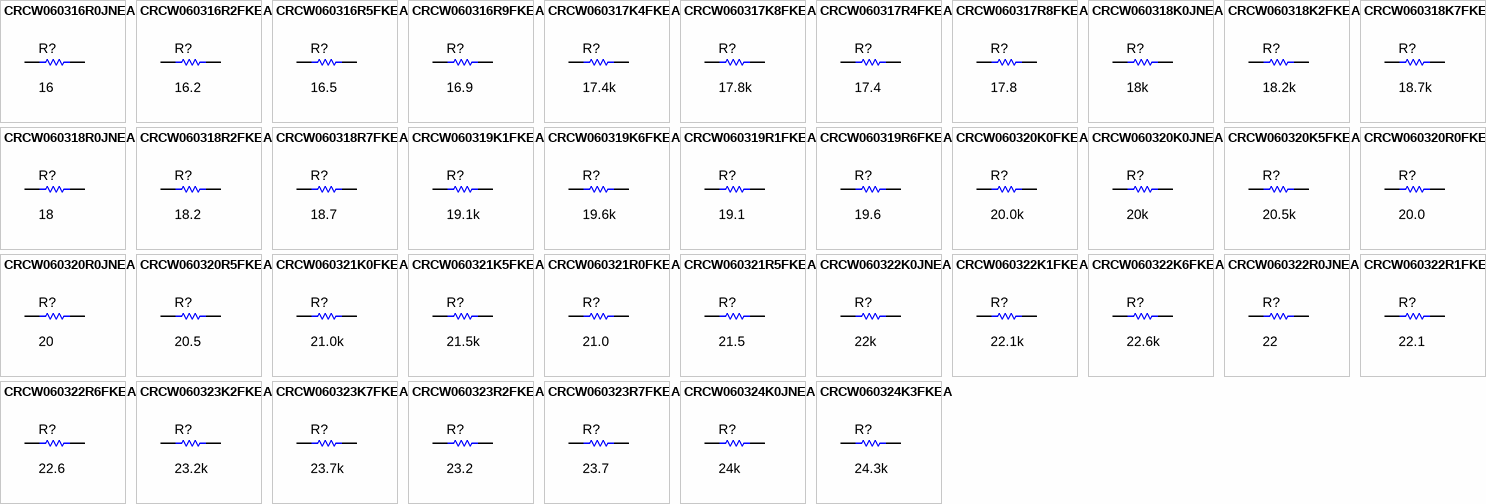
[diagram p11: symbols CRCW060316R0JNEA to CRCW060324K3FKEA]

## CRCW060316R0JNEA
designator R?  ValueDisplayed: 16  (hidden comment: CRCW060316R0JNEA)
RES, 16, 5%, 0.1 W, 0603; Manufacturer: Vishay-Dale; CompType: Resistor; Value: 16; Value_Code: 16R0; Tolerance_%: 5; Power_W: 0.1; Value2: 0.1W; VDC_V: 75; TempCo: 200 ppm/C; SizeArea_mm2: 1.28; SizeX_mm: 1.6; SizeY_mm: 0.8; SizeZ_mm: 1; EIA_Code: E24; U/M: EA; AEC Category: Q200
signal-integrity model Resistor
simulation model Resistor
footprint 0603
footprint 0603M
footprint 0603L
footprint 0603_HV
footprint 0603S
pins: 1, 2

## CRCW060316R2FKEA
designator R?  ValueDisplayed: 16.2  (hidden comment: CRCW060316R2FKEA)
RES, 16.2, 1%, 0.1 W, 0603; Manufacturer: Vishay-Dale; CompType: Resistor; Value: 16.2; Value_Code: 16R2; Tolerance_%: 1; Power_W: 0.1; Value2: 0.1W; VDC_V: 75; TempCo: 100 ppm/C; SizeArea_mm2: 1.28; SizeX_mm: 1.6; SizeY_mm: 0.8; EIA_Code: E96; U/M: EA; AEC Category: Q200
signal-integrity model Resistor
simulation model Resistor
footprint 0603
footprint 0603M
footprint 0603L
footprint 0603_HV
footprint 0603S
pins: 1, 2

## CRCW060316R5FKEA
designator R?  ValueDisplayed: 16.5  (hidden comment: CRCW060316R5FKEA)
RES, 16.5, 1%, 0.1 W, 0603; Manufacturer: Vishay-Dale; CompType: Resistor; Value: 16.5; Value_Code: 16R5; Tolerance_%: 1; Power_W: 0.1; Value2: 0.1W; VDC_V: 75; TempCo: 100 ppm/C; SizeArea_mm2: 1.28; SizeX_mm: 1.6; SizeY_mm: 0.8; EIA_Code: E96; U/M: EA; AEC Category: Q200
signal-integrity model Resistor
simulation model Resistor
footprint 0603
footprint 0603M
footprint 0603L
footprint 0603_HV
footprint 0603S
pins: 1, 2

## CRCW060316R9FKEA
designator R?  ValueDisplayed: 16.9  (hidden comment: CRCW060316R9FKEA)
RES, 16.9, 1%, 0.1 W, 0603; Manufacturer: Vishay-Dale; CompType: Resistor; Value: 16.9; Value_Code: 16R9; Tolerance_%: 1; Power_W: 0.1; Value2: 0.1W; VDC_V: 75; TempCo: 100 ppm/C; SizeArea_mm2: 1.28; SizeX_mm: 1.6; SizeY_mm: 0.8; EIA_Code: E96; U/M: EA; AEC Category: Q200
signal-integrity model Resistor
simulation model Resistor
footprint 0603
footprint 0603M
footprint 0603L
footprint 0603_HV
footprint 0603S
pins: 1, 2

## CRCW060317K4FKEA
designator R?  ValueDisplayed: 17.4k  (hidden comment: CRCW060317K4FKEA)
RES, 17.4 k, 1%, 0.1 W, 0603; Manufacturer: Vishay-Dale; CompType: Resistor; Value: 17.4k; Res_ohm: 17400; Value_Code: 17k4; Tolerance_%: 1; Power_W: 0.1; Value2: 0.1W; VDC_V: 75; TempCo: 100 ppm/C; SizeArea_mm2: 1.28; SizeX_mm: 1.6; SizeY_mm: 0.8; EIA_Code: E96; U/M: EA; AEC Category: Q200; Green_Lifecycle: Active; Green_REACh: Passed
signal-integrity model Resistor
simulation model Resistor
footprint 0603
footprint 0603M
footprint 0603L
footprint 0603_HV
footprint 0603S
pins: 1, 2

## CRCW060317K8FKEA
designator R?  ValueDisplayed: 17.8k  (hidden comment: CRCW060317K8FKEA)
RES, 17.8 k, 1%, 0.1 W, 0603; Manufacturer: Vishay-Dale; CompType: Resistor; Value: 17.8k; Res_ohm: 17800; Value_Code: 17k8; Tolerance_%: 1; Power_W: 0.1; Value2: 0.1W; VDC_V: 75; TempCo: 100 ppm/C; SizeArea_mm2: 1.28; SizeX_mm: 1.6; SizeY_mm: 0.8; EIA_Code: E96; U/M: EA; AEC Category: Q200; Green_Lifecycle: Active; Green_REACh: Passed
signal-integrity model Resistor
simulation model Resistor
footprint 0603
footprint 0603M
footprint 0603L
footprint 0603_HV
footprint 0603S
pins: 1, 2

## CRCW060317R4FKEA
designator R?  ValueDisplayed: 17.4  (hidden comment: CRCW060317R4FKEA)
RES, 17.4, 1%, 0.1 W, 0603; Manufacturer: Vishay-Dale; CompType: Resistor; Value: 17.4; Value_Code: 17R4; Tolerance_%: 1; Power_W: 0.1; Value2: 0.1W; VDC_V: 75; TempCo: 100 ppm/C; SizeArea_mm2: 1.28; SizeX_mm: 1.6; SizeY_mm: 0.8; EIA_Code: E96; U/M: EA; AEC Category: Q200
signal-integrity model Resistor
simulation model Resistor
footprint 0603
footprint 0603M
footprint 0603L
footprint 0603_HV
footprint 0603S
pins: 1, 2

## CRCW060317R8FKEA
designator R?  ValueDisplayed: 17.8  (hidden comment: CRCW060317R8FKEA)
RES, 17.8, 1%, 0.1 W, 0603; Manufacturer: Vishay-Dale; CompType: Resistor; Value: 17.8; Value_Code: 17R8; Tolerance_%: 1; Power_W: 0.1; Value2: 0.1W; VDC_V: 75; TempCo: 100 ppm/C; SizeArea_mm2: 1.28; SizeX_mm: 1.6; SizeY_mm: 0.8; EIA_Code: E96; U/M: EA; AEC Category: Q200
signal-integrity model Resistor
simulation model Resistor
footprint 0603
footprint 0603M
footprint 0603L
footprint 0603_HV
footprint 0603S
pins: 1, 2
